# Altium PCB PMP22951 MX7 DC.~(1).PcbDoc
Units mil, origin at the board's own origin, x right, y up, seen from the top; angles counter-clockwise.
Board outline 4950 x 3450 mil, 2 copper layers (Top Layer, Bottom Layer), stack 62 mil thick; 24 components, 0 nets, 16 pads, 0 vias.
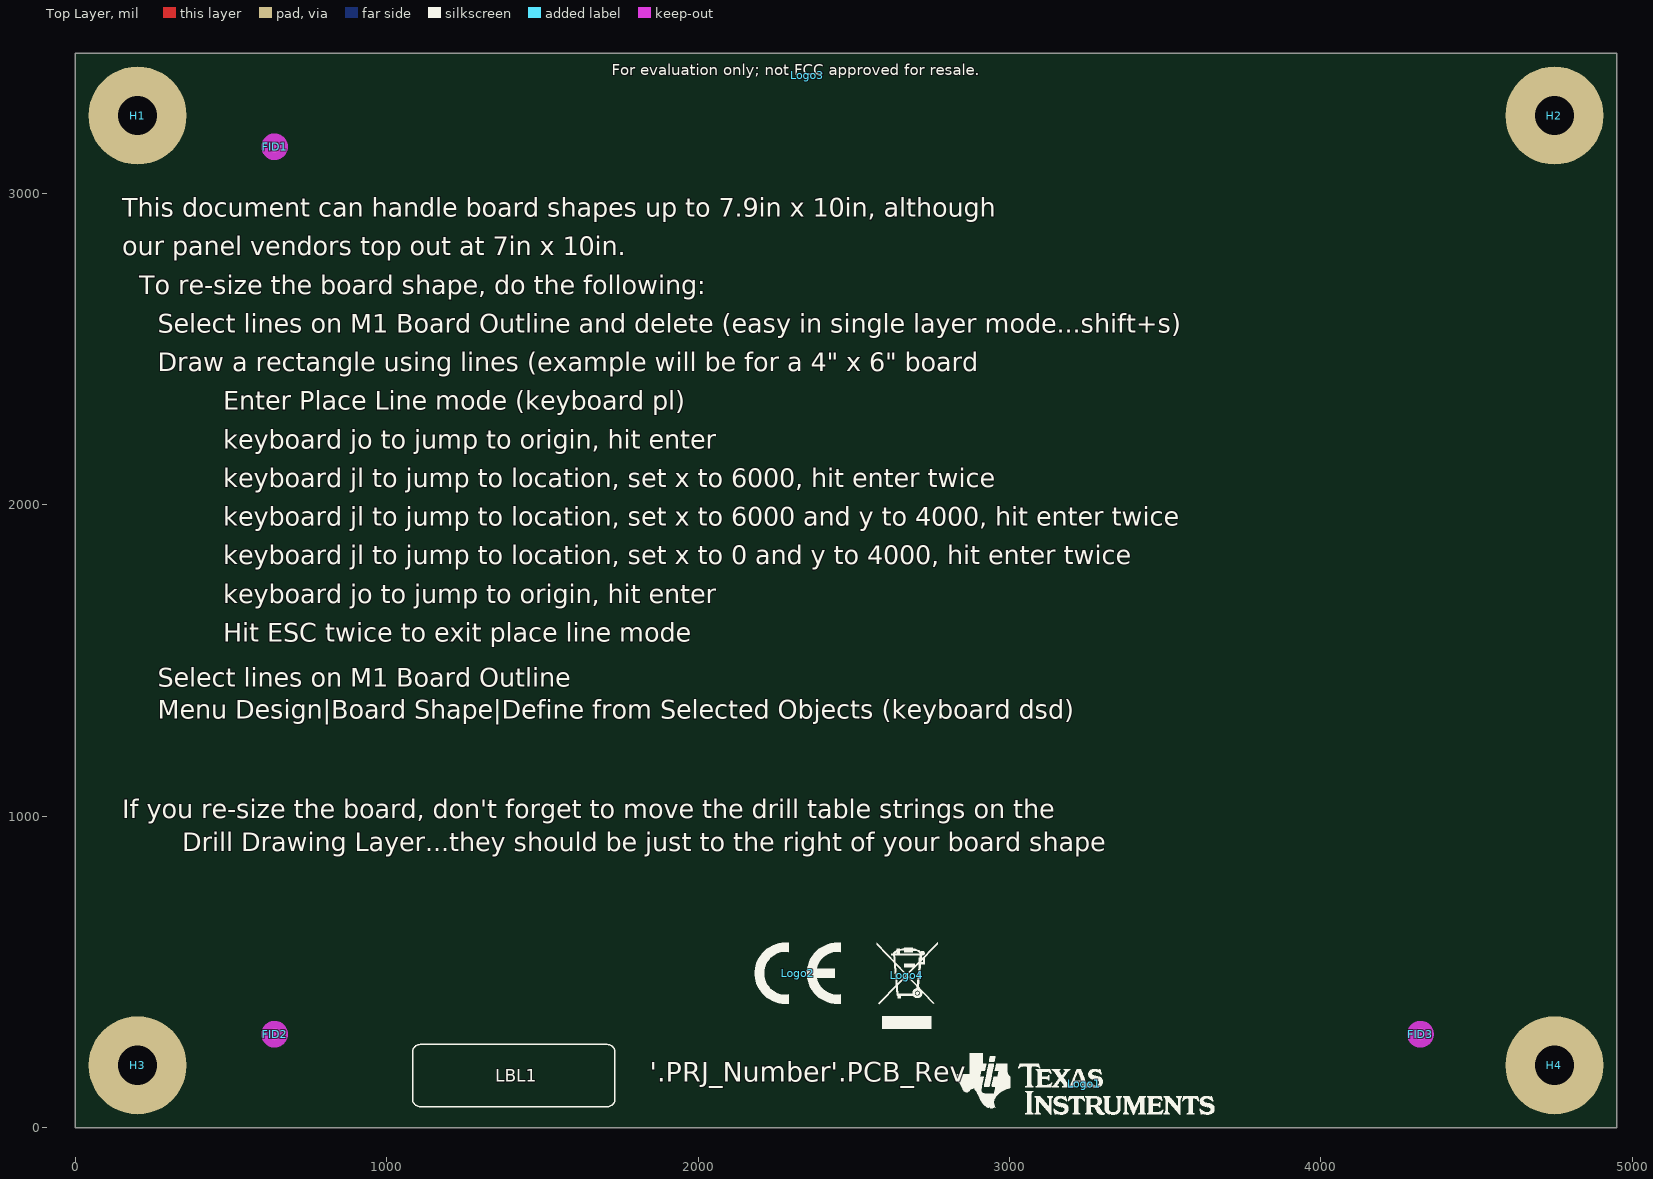
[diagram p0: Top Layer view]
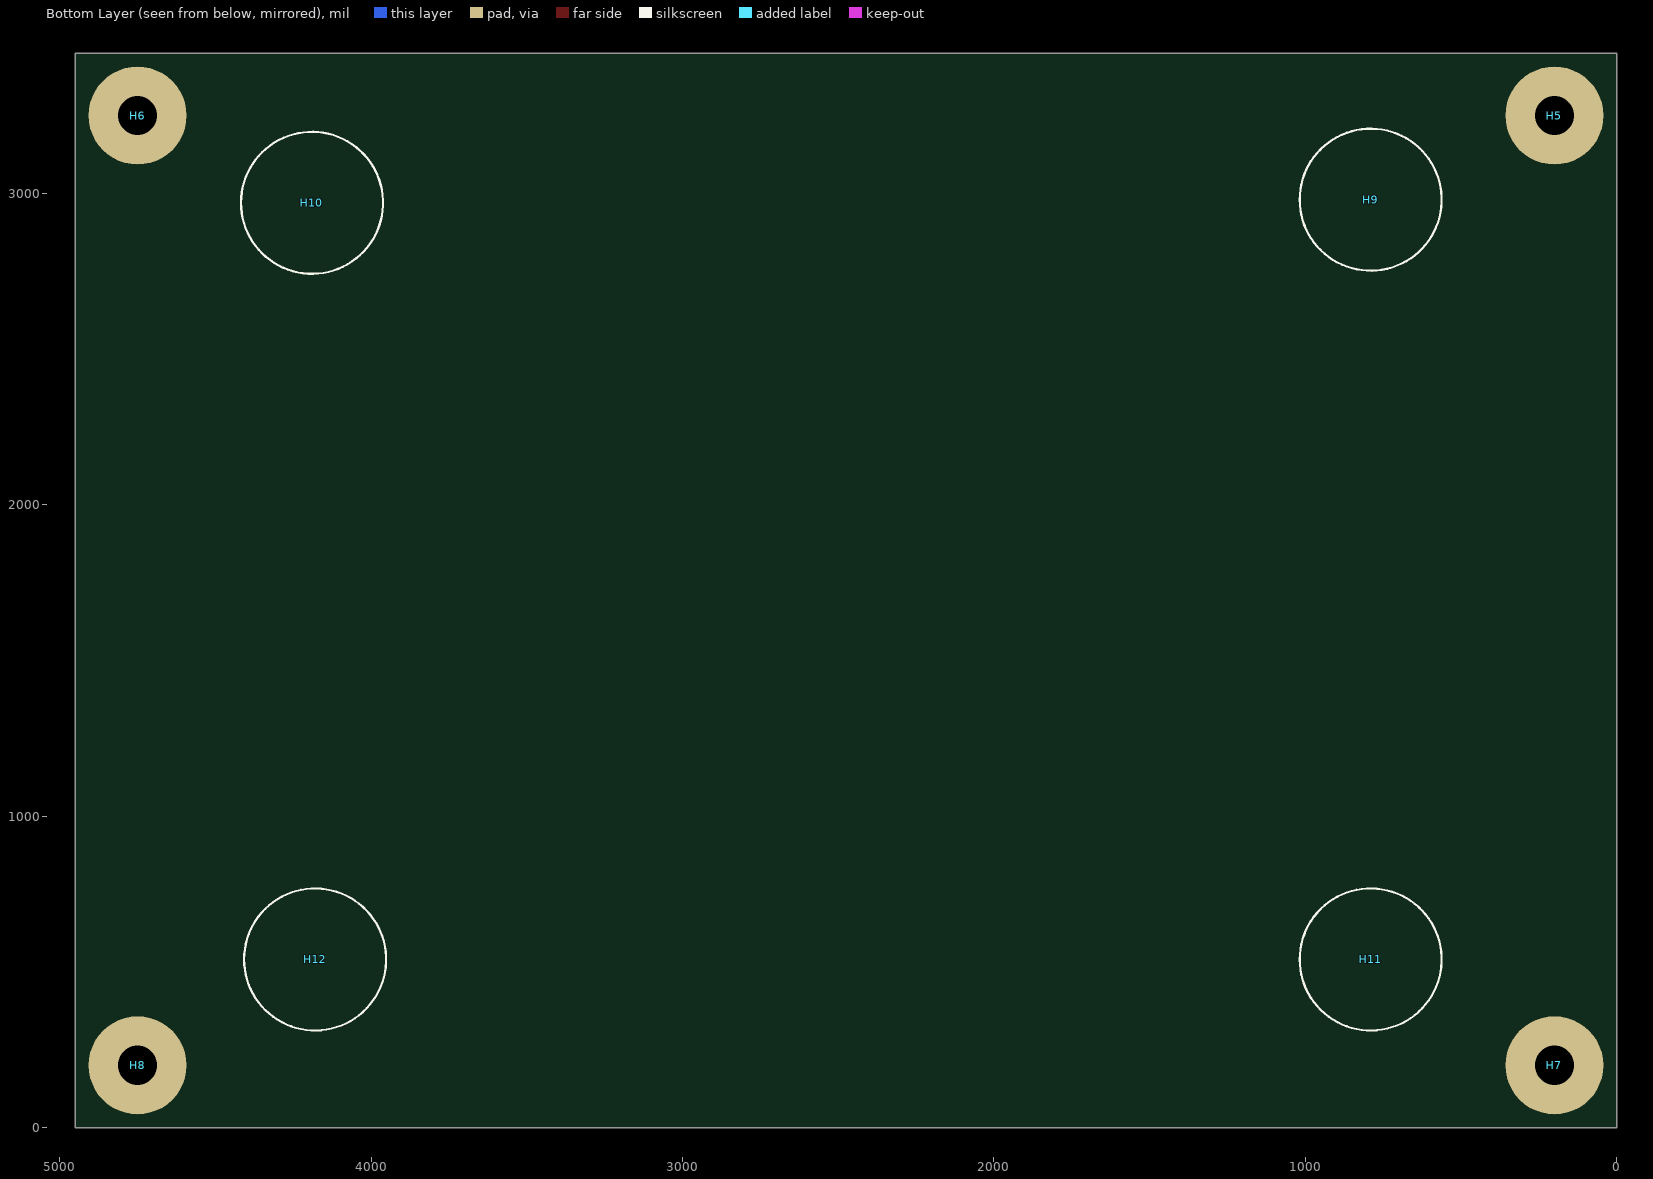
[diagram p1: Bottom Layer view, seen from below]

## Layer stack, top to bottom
Top Solder: solder mask 0.4, Solder Resist, Dk 3.5
Top Layer: signal copper 1.4
Dielectric1: core 59.2, FR-4 High Tg, Dk 4.8
Bottom Layer: signal copper 1.4
Bottom Solder: solder mask 0.4, Solder Resist, Dk 3.5

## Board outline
0,0 4950,0 4950,3450 0,3450

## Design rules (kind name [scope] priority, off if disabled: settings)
AcuteAngle [All] p1: minimum=4.50000000000000E+0001 checktracksonly=FALSE
AssemblyTestPointUsage [All] p1: valid=2
BoardOutlineClearance BoardOutlineClearance_MountingHoles [OnCopper and InComponentClass('Mounting Holes')] p1: gap=39.37 ignorepadtopadclearanceinfootprint=FALSE
BoardOutlineClearance BoardOutlineClearance_Poly [OnCopper and IsPoly] p2: gap=25 ignorepadtopadclearanceinfootprint=FALSE
BoardOutlineClearance [OnCopper and Not InComponentClass('Logo') and not InComponentClass('FiducialMark') and not InRegion(1000,500,4000,800) and not InPoly] p3: gap=40 ignorepadtopadclearanceinfootprint=FALSE
Clearance Clearance_Keepouts [((IsTrack Or IsArc) And Not InPoly) And IsFree and IsKeepOut vs ((IsTrack Or IsArc) And Not InPoly) And IsFree and IsKeepOut] p1: gap=0 ignorepadtopadclearanceinfootprint=FALSE
Clearance Clearance_Poly [InPolygon] p2: gap=10 ignorepadtopadclearanceinfootprint=TRUE
Clearance Clearance_FiducialMark [IsKeepOut and InComponentClass('FiducialMark') vs IsPad and InComponentClass('FiducialMark')] p3: gap=0 ignorepadtopadclearanceinfootprint=FALSE
Clearance [All] p4: gap=7.87 ignorepadtopadclearanceinfootprint=TRUE
ComponentClearance ComponentClearance_MountingHoles_FiducialMarks [InComponentClass('Mounting Holes') vs InComponentClass('FiducialMark')] p1: gap=50 collisioncheckmode=3 verticalgap=10 showdistances=FALSE
ComponentClearance ComponentClearance_Shunt [InComponentClass('Header') vs InComponentClass('Shunt')] p2: gap=0 collisioncheckmode=3 verticalgap=0 showdistances=FALSE
ComponentClearance ComponentClearance_Logo [InComponentClass('Logo')] p3: gap=30 collisioncheckmode=3 verticalgap=10 showdistances=FALSE
ComponentClearance ComponentClearance_ScrewToNut [(HasFootprint('NY PMS 440 0025 PH')) vs (HasFootprint('Keystone_1902C'))] p4: gap=5 collisioncheckmode=3 verticalgap=10 showdistances=FALSE
ComponentClearance ComponentClearance_MountingHoles [InComponentClass('Mounting Holes')] p5: gap=100 collisioncheckmode=3 verticalgap=100000 showdistances=FALSE
ComponentClearance ComponentClearance_SmallPassives [HasFootprint('0201*') or HasFootprint('0402*') or HasFootprint('0508') or HasFootprint('0603*') or HasFootprint('0612') or HasFootprint('0805*') or HasFootprint('0815*') or HasFootprint('0830*') or HasFootprint('1206*') or HasFootprint('1210*') or HasFootprint('1808*') or HasFootprint('1812*') or HasFootprint('1825*') or HasFootprint('2010*') or HasFootprint('2220*') or HasFootprint('2225*') or HasFootprint('2512*') or HasFootprint('2728*') or HasFootprint('3518*') vs HasFootprint('0201*') or HasFootprint('0402*') or HasFootprint('0508') or HasFootprint('0603*') or HasFootprint('0612') or HasFootprint('0805*') or HasFootprint('0815*') or HasFootprint('0830*') or HasFootprint('1206*') or HasFootprint('1210*') or HasFootprint('1808*') or HasFootprint('1812*') or HasFootprint('1825*') or HasFootprint('2010*') or HasFootprint('2220*') or HasFootprint('2225*') or HasFootprint('2512*') or HasFootprint('2728*') or HasFootprint('3518*')] p6: gap=14.96 collisioncheckmode=3 verticalgap=10 showdistances=FALSE
ComponentClearance ComponentClearance_THtoSMT [IsThruComponent vs IsSMTComponent] p7: gap=30 collisioncheckmode=3 verticalgap=30 showdistances=FALSE
ComponentClearance ComponentClearance_THtoTH [IsThruComponent vs IsThruComponent] p8: gap=20 collisioncheckmode=3 verticalgap=30 showdistances=FALSE
ComponentClearance [All] p9: gap=20 collisioncheckmode=3 verticalgap=10 showdistances=FALSE
DiffPairsRouting [All] p1: maxlimit=100 minlimit=10 mostfreqgap=10 toplayer_minwidth=15 toplayer_maxwidth=15 toplayer_prefwidth=15 bottomlayer_minwidth=15 bottomlayer_maxwidth=15 bottomlayer_prefwidth=15 maxuncoupledlength=1000
FabricationTestPointUsage TestPointUsage [All] p1: valid=2 allowmultiple=FALSE
FabricationTestpoint Testpoint [All] p1: side=3 testpointundercomponent=TRUE minsize=40 maxsize=100 preferedsize=60 minholesize=0 maxholesize=40 preferedholesize=32 testpointgrid=1 allowsidetop=TRUE allowsidebottom=TRUE usegrid=TRUE gridtolerance=0.01
FanoutControl Fanout_LCC [IsLCC] p1: bgadir=Out bgaviamode=Centered fanoutstyle=Auto fanoutdirection=Alternating viagrid=1 // Fanout_LCC (Default Rule)
FanoutControl Fanout_BGA [IsBGA] p2: bgadir=Out bgaviamode=Centered fanoutstyle=Auto fanoutdirection=Alternating viagrid=1 // Fanout_BGA (Default Rule)
FanoutControl Fanout_Default [All] p4: bgadir=Out bgaviamode=Centered fanoutstyle=Auto fanoutdirection=Alternating viagrid=1 // Fanout_Default (Default Rule)
FanoutControl Fanout_Small [(CompPinCount < 5)] p5: bgadir=Out bgaviamode=Centered fanoutstyle=Auto fanoutdirection=OutThenIn viagrid=1 // Fanout_Small (Default Rule)
HoleSize [All] p1: absolutevalues=TRUE maxlimit=251 minlimit=7.87 maxpercent=80.000 minpercent=20.000
MinimumAnnularRing MinimumAnnularRing_ThermalPadVias [IsVia and InAnyComponent] p1: minimumring=5.91
MinimumAnnularRing [All] p2: minimumring=7.87
MinimumSolderMaskSliver MinimumSolderMaskSliver_Logo [InComponentClass('Logo') vs InComponentClass('Logo')] p1: minsoldermaskwidth=0.7
MinimumSolderMaskSliver [All] p2: minsoldermaskwidth=3.94
PlaneConnect [All] p1: planeconnectstyle=Relief reliefexpansion=10 reliefentries=4 reliefconductorwidth=10 reliefairgap=10
PolygonConnect [All] p1: connectstyle=Relief reliefconductorwidth=10 reliefentries=4 polygonreliefangle="90 Angle" airgapwidth=10
RoutingVias ThermalPadVias [IsVia and InAnyComponent] p1: holewidth=7.87 width=19.68 viastyle="Through Hole" minholewidth=7.87 minwidth=19.68 maxholewidth=12.99 maxwidth=23.62
RoutingVias [All] p2: holewidth=16 width=34 viastyle="Through Hole" minholewidth=7.87 minwidth=24 maxholewidth=40 maxwidth=65
SilkToBoardRegionClearance [Not ((IsComment or IsDesignator) And (Hide <> 'False')) and not InRegion(1000,500,4000,800)] p1:
SilkToSilkClearance SilkToSilkClearance_Pb-FreeLogo [(HasFootprint('Pb-Free_Overlay_Medium') OR HasFootprint('Pb-Free_Overlay_Small')) vs (HasFootprint('Pb-Free_Overlay_Medium') OR HasFootprint('Pb-Free_Overlay_Small'))] p1: silktosilkclearance=0
SilkToSilkClearance [All] p2: silktosilkclearance=3.94
SilkToSolderMaskClearance SilkToComponentPadClearance [(IsPad or IsFill or IsRegion) and InAnycomponent] p1: minsilkscreentomaskgap=5 clearancetoexposedcopper=TRUE
SilkToSolderMaskClearance "Silk to Solder Mask Opening" [All] p2: minsilkscreentomaskgap=3.94 clearancetoexposedcopper=FALSE
SolderMaskExpansion [All] p1: expansion=1.97 istentingtop=FALSE
UnRoutedNet [All] p1: checkbadconnections=TRUE
Width [All] p1: maxlimit=100 minlimit=6 preferedwidth=10 checkconnectedcopper=TRUE
14 further rules are at their usual default settings.

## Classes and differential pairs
component class "Mounting Holes": H1 H2 H3 H4
component class Logo: Logo1
component class FiducialMark: FID1 FID2 FID3
component class AssemblyNote: ZZ1 ZZ2 ZZ3 ZZ4
component class Label: LBL1

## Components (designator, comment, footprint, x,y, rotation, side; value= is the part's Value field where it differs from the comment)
FID1 "Fiducial" Fiducial10-20 640,3150 r0 top
FID2 "Fiducial" Fiducial10-20 640,300 r0 top
FID3 "Fiducial" Fiducial10-20 4320,300 r0 top
H1 "NY PMS 440 0025 PH" "NY PMS 440 0025 PH" 200,3250 r0 top locked
H2 "NY PMS 440 0025 PH" "NY PMS 440 0025 PH" 4750,3250 r0 top locked
H3 "NY PMS 440 0025 PH" "NY PMS 440 0025 PH" 200,200 r0 top locked
H4 "NY PMS 440 0025 PH" "NY PMS 440 0025 PH" 4750,200 r0 top locked
H5 "1902C" Keystone_1902C 200,3250 r180 bottom locked
H6 "1902C" Keystone_1902C 4750,3250 r180 bottom locked
H7 "1902C" Keystone_1902C 200,200 r180 bottom locked
H8 "1902C" Keystone_1902C 4750,200 r180 bottom locked
H9 "SJ-5303 (CLEAR)" Bumpon_SJ5003Transparent 790,2980 r180 bottom
H10 "SJ-5303 (CLEAR)" Bumpon_SJ5003Transparent 4190,2970 r180 bottom
H11 "SJ-5303 (CLEAR)" Bumpon_SJ5003Transparent 790,540 r180 bottom
H12 "SJ-5303 (CLEAR)" Bumpon_SJ5003Transparent 4180,540 r180 bottom
LBL1 "THT-14-423-10" Label_650x200 1408,167 r0 top
Logo1 "Texas Instruments" TI_Stacked_Overlay_Small 3240,140 r0 top
Logo2 "CE Mark" CE_Mark_5mm 2320,495.68 r0 top
Logo3 "FCC disclaimer" FCC_disclaimer 2350,3380 r0 top
Logo4 "WEEE logo" WEEE_Minimum 2670,490 r0 top
ZZ1 "This Assembly Note is for PCB labels only" AssemblyNoteLabel 185,3938 r0 top
ZZ2 "These assemblies are ESD sensitive, ESD precautions shall be observed." AssemblyNote 185,3829.11 r0 top
ZZ3 "These assemblies must be clean and free from flux and all contaminants. Use of no clean flux is not acceptable." AssemblyNote 185,3740.56 r0 top
ZZ4 "These assemblies must comply with workmanship standards IPC-A-610 Class 2, unless otherwise specified." AssemblyNote 185,3652 r0 top

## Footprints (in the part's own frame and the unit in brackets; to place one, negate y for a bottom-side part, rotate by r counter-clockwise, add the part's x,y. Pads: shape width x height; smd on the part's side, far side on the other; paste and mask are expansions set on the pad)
AssemblyNote [mil] "Assembly Note"
AssemblyNoteLabel [mil] "Assembly Note for PCB Labels"
Bumpon_SJ5003Transparent [mil] "3M Hemispherical Bumpon transparent"
  round 1 on Mech4: 0(0,0)
  silkscreen extent -228,-228 228,228, body extent -219,-219 219,219, height 197
CE_Mark_5mm [mil] "Minimum text height for CE Mark"
  silkscreen extent -138,-98 138,98
FCC_disclaimer [mil]
Fiducial10-20 [mm]
  round 1 smd mask+0.5: 1(0,0)
  Top Layer keep-out circle w1.178: c0,0 r0.5
Keystone_1902C [mil] "Hex Standoff, 4-40 threaded, nylon"
  round 1 on Mech4: 0(0,0)
  body extent -145,-126 146,126, height 501
Label_650x200 [mil] "Thermal Transfer Label"
  round 1 on Mech13: 0(0,0)
  silkscreen extent -325,-100 325,100, body extent -325,-100 325,100, height 1
"NY PMS 440 0025 PH" [mm] "4-40 nylon screw and mounting hole"
  round 8 hole 3.2: 1(0,0)
  body extent -3.3,-3.3 3.3,3.3, height 2.69
TI_Stacked_Overlay_Small [mil]
  silkscreen extent -418,-98 418,98
WEEE_Minimum [mil] "WEEElie bin"
  silkscreen extent -95,-172 99,104

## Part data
FID1 FID2 FID3: library part CMP-0077181-1, "Fiducial mark.  There is nothing to buy or mount.", Manufacturer=N/A
H1 H2 H3 H4: library part CMP-0003617-1, "Machine Screw, Round, #4-40 x 1/4, Nylon, Philips panhead", Manufacturer="B&F Fastener Supply", Supplier Part Number 1=H542-ND
H5 H6 H7 H8: library part CMP-0003610-1, "Standoff, Hex, 0.5\"L #4-40 Nylon", Manufacturer=Keystone, Supplier Part Number 1=36-1902C-ND
H9 H10 H11 H12: library part CMP-0003620-1, "Bumpon, Hemisphere, 0.44 X 0.20, Clear", Manufacturer=3M, Supplier Part Number 1=SJ5303-7-ND
LBL1: library part CMP-0003625-1, "Thermal Transfer Printable Labels, 0.650\" W x 0.200\" H - 10,000 per roll", Manufacturer=Brady, Supplier Part Number 1=97C5133
Logo1: library part CMP-0074838-1, "Texas Instrument Corporate Signature"
Logo2: library part CMP-0074844-1
Logo3: library part CMP-0074847-1, "FCC_disclaimer"
Logo4: library part CMP-0074769-1
ZZ1: library part CMP-0003616-3
ZZ2: library part CMP-0077236-1
ZZ3: library part CMP-0077237-1
ZZ4: library part CMP-0077238-1

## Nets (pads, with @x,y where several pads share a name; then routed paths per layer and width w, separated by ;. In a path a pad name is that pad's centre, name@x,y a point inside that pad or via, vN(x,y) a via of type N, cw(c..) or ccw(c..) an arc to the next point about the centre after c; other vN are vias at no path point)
pads on no net: FID1.1 FID2.1 FID3.1 H1.1 H2.1 H3.1 H4.1 H5.0 H6.0 H7.0 H8.0 H9.0 H10.0 H11.0 H12.0 LBL1.0

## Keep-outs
Keep-Out Layer:
  text ".Layer_Name" at 577,-858.49 h60

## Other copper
Top Layer:
  text ".Layer_Name" at 577,-858.49 h60
Bottom Layer:
  text ".Layer_Name" at 577,-858.49 h60

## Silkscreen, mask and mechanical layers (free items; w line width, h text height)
Top Overlay:
  text "This document can handle board shapes up to 7.9in x 10in, although" at 150,2925 h60
  text "our panel vendors top out at 7in x 10in." at 150,2800.94 h60
  text "To re-size the board shape, do the following:" at 205,2676.88 h60
  text "Select lines on M1 Board Outline and delete (easy in single layer mode...shift+s)" at 265,2552.82 h60
  text "Draw a rectangle using lines (example will be for a 4\" x 6\" board" at 265,2428.76 h60
  text "Enter Place Line mode (keyboard pl)" at 475,2304.71 h60
  text "keyboard jo to jump to origin, hit enter" at 475,2180.65 h60
  text "keyboard jl to jump to location, set x to 6000, hit enter twice" at 475,2056.59 h60
  text "keyboard jl to jump to location, set x to 6000 and y to 4000, hit enter twice" at 475,1932.53 h60
  text "keyboard jl to jump to location, set x to 0 and y to 4000, hit enter twice" at 475,1808.47 h60
  text "keyboard jo to jump to origin, hit enter" at 475,1684.41 h60
  text "Hit ESC twice to exit place line mode" at 475,1560.35 h60
  text "Select lines on M1 Board Outline" at 265,1416.3 h60
  text "Menu Design|Board Shape|Define from Selected Objects (keyboard dsd)" at 265,1312.24 h60
  text "If you re-size the board, don't forget to move the drill table strings on the" at 150,993 h60
  text "Drill Drawing Layer...they should be just to the right of your board shape" at 343,887 h60
  text "'.PRJ_Number'.PCB_Rev" at 1845,125.77 h108.27
  text ".Layer_Name" at 577,-858.49 h60
Bottom Overlay:
  text ".Layer_Name" at 577,-858.49 h60
Top Paste:
  text ".Layer_Name" at 577,-858.49 h60
Bottom Paste:
  text ".Layer_Name" at 577,-858.49 h60
Top Solder:
  text ".Layer_Name" at 577,-858.49 h60
  text ".Layer_Name" at 577,-858.49 h60
Bottom Solder:
  text ".Layer_Name" at 577,-858.49 h60
Drill Guide:
  text ".Layer_Name" at 577,-858.49 h60
M1 Board Outline:
  the board outline again, w10
  text ".Layer_Name" at 577,-858.49 h60
M2 Board Dimensions:
  rectangle: 0,-275 125,-150
  rectangle: 125,-400 500,-275
  lines w7: 0,-275 1000,-275 ; 125,-400 125,-150 ; 250,-400 250,-150 ; 500,-400 500,-150 ; 750,-400 750,-150 ; 0,-400 1000,-400 1000,-150 0,-150 0,-400
  text ".Layer_Name" at 577,-858.49 h60
M3 3D STEP Top:
  text ".Layer_Name" at 577,-858.49 h60
M4 3D STEP Bottom:
  text ".Layer_Name" at 577,-858.49 h60
M5 Assembly Top:
  lines w10: -292,-930.17 6308,-930.17 ; -292,-726.83 6310,-726.83 ; -292,-523.5 -292,-1133.5 3713,-1133.5 6310,-1133.5 6310,-523.5 -291.5,-523.5 -291.5,-1133.5 1284,-1133.5 ; 2173,-1133.5 2173,-523.5 ; 3440,-726.83 3440,-523.5 ; 4280,-726.83 4280,-523.5 ; 4902,-1140 4902,-937.17
  text "COMPONENTS MARKED 'DNP' SHOULD NOT BE POPULATED." at 1153.5,-318.5 h60
  text "ASSEMBLY VARIANT:" at 1153,-434 h60
  text ".VariantName" at 2189,-434 h60
  text "PCB VIEWED FROM TOP SIDE" at -228.5,-655.67 h60
  text "BOARD #:" at 2248,-655.67 h60
  text ".PRJ_Number" at 2793.5,-655.67 h60
  text "REV:" at 3638,-655.67 h60
  text ".PCB_Rev" at 3929.5,-655.67 h60
  text "SVN REV:" at 4476,-655.67 h60
  text ".VersionControl_RevNumber" at 4982,-655.67 h60
  text "TID #:" at 2248,-859 h60
  text ".TID" at 2793.5,-859 h60
  text "PLOT NAME =" at -228.5,-1064.34 h60
  text ".plot_File_Name" at 577,-1064.34 h60
  text "GENERATED    :" at 2250,-1064.34 h60
  text ".Print_Date" at 3119.5,-1064.34 h60
  text ".Print_Time" at 3848.5,-1064.34 h60
  text "TEXAS INSTRUMENTS" at 5113,-1064.34 h60
M6 Assembly Bottom:
  lines w10: -292.5,-727.33 6309.5,-727.33 ; -290.5,-930.67 6309.5,-930.67 ; 1115.5,-1140.5 1115.5,-937.67 ; 1737.5,-727.33 1737.5,-524 ; 2577.5,-727.33 2577.5,-524 ; 3844.5,-1134 3844.5,-524 ; 4733.5,-1134 6309,-1134 6309,-524 -292.5,-524 -292.5,-1134 2304.5,-1134 6309.5,-1134 6309.5,-524
  text "COMPONENTS MARKED 'DNP' SHOULD NOT BE POPULATED." at 6102,-318 h60
  text ".VariantName" at 5058,-434 h60
  text "ASSEMBLY VARIANT:" at 6097,-434 h60
  text ".VersionControl_RevNumber" at 1035.5,-656.17 h60
  text "SVN REV:" at 1541.5,-656.17 h60
  text ".PCB_Rev" at 2088,-656.17 h60
  text "REV:" at 2379.5,-656.17 h60
  text ".PRJ_Number" at 3224,-656.17 h60
  text "BOARD #:" at 3769.5,-656.17 h60
  text "PCB VIEWED FROM BOTTOM SIDE" at 6246,-656.17 h60
  text ".TID" at 3224,-859.5 h60
  text "TID #:" at 3769.5,-859.5 h60
  text "TEXAS INSTRUMENTS" at 904.5,-1064.84 h60
  text ".Print_Time" at 2169,-1064.84 h60
  text ".Print_Date" at 2898,-1064.84 h60
  text "GENERATED    :" at 3767.5,-1064.84 h60
  text ".plot_File_Name" at 5440.5,-1064.84 h60
  text "PLOT NAME =" at 6246,-1064.84 h60
M9 Title Sheet:
  drawing of 57 lines, arcs and shapes, not listed
  text "1" at 739.84,8036.5 h70
  text "2" at 3235.5,8036.5 h70
  text "3" at 5724.84,8036.5 h70
  text "4" at 8231.51,8036.5 h70
  text "5" at 10730.5,8036.5 h70
  text "6" at 13235.5,8036.5 h70
  text "A" at -416.5,6893.5 h70
  text "A" at 14383.5,6893.5 h70
  text "B" at -416.5,4513.5 h70
  text "B" at 14383.5,4513.5 h70
  text "C" at -416.5,2138.5 h70
  text "C" at 14383.5,2138.5 h70
  text "PROJECT TITLE:" at 11343.5,277.5 h45
  text ".PRJ_Title" at 11393.5,144.17 h70
  text "DESIGNED FOR:" at 11343.5,-23.5 h45
  text ".PRJ_Customer" at 11393.5,-163.5 h70
  text "D" at -416.5,-231.5 h70
  text "D" at 14383.5,-231.5 h70
  text "FILE NAME:" at 11343.5,-323.5 h45
  text ".PCB_File_Name_No_Path" at 11393.5,-443.5 h70
  text "Texas Instruments (TI) and/or its licensors do not warrant the accuracy or completeness of this specification" at 6374,-605.34 h45
  text "ENGINEER:" at 11343.5,-613.5 h45
  text "LAYOUT BY:" at 12848.5,-613.5 h45
  text "or any information contained therein. TI and/or its licensors do not warrant that this design will meet" at 6329.01,-718 h45
  text ".PRJ_Engineer" at 11393.5,-768.49 h70
  text ".PCB_Layout" at 12899,-768.49 h70
  text "the specifications, will be suitable for your application or fit for any particular purpose, or will operate in" at 6329.01,-830.67 h45
  text ".Layer_Name" at 577,-858.49 h60
  text "ALTIUM DESIGNER VERSION:" at 12848.5,-923.5 h45
  text "an implementation. TI and/or its licensors do not warrant that the design is production worthy. You should" at 6329.01,-943.33 h45
  text "completely validate and test your design implementation to confirm the system functionality for your application." at 6374,-1056 h45
  text ".print_Scale" at 11393.5,-1056.83 h70
  text ".Application_BuildNumber" at 12899,-1056.83 h70
  text "1" at 739.84,-1263.5 h70
  text "2" at 3235.5,-1263.5 h70
  text "3" at 5724.84,-1263.5 h70
  text "4" at 8231.51,-1263.5 h70
  text "5" at 10730.5,-1263.5 h70
  text "6" at 13235.5,-1263.5 h70
M10 Fab Notes:
  drawing of 189 lines, arcs and shapes, not listed
  text "DESIGN INFORMATION" at 12382.02,6356.17 h60
  text "MIN. TRACK WIDTH:" at 11737.46,6224.05 h60
  text "8" at 12833.7,6224.05 h60
  text "MIL" at 12988.46,6224.05 h60
  text "7.874" at 12667.32,6102.36 h60
  text "MIN. CLEARANCE:" at 11737.46,6099.92 h60
  text "MIL" at 12988.46,6099.92 h60
  text "MIN. VIA PAD SIZE:" at 11737.46,5975.8 h60
  text "24" at 12803.71,5975.8 h60
  text "MIL" at 12988.46,5975.8 h60
  text "0.05mm (2MIL)" at 12432.46,5845.9 h60
  text "MINIMUM ANNULAR RING" at 11408.23,5837.67 h60
  text "EXTERNAL" at 13140.46,5837.67 h60
  text "PER" at 11608.23,5727.55 h60
  text "IPC-D-275 CLASS 2 LEVEL C" at 11828.23,5727.54 h60
  text "MIL, HOLES" at 13316.46,5627.07 h60
  text "+/-" at 12924,5618.48 h60
  text "+/-" at 13778,5618.48 h60
  text "REGISTRATION TOLERANCES:" at 11408.23,5617.42 h60
  text "METAL" at 12608,5617.42 h60
  text "5" at 13184.2,5617.42 h60
  text "3" at 14017.2,5617.42 h60
  text "MIL" at 14133.46,5617.42 h60
  text "HOLE SIZE TOLERANCE (UNLESS OTHERWISE SPECIFIED):" at 11408.23,5519.1 h60
  text "+/-" at 13778,5516.23 h60
  text "3" at 14017.2,5515.17 h60
  text "MIL" at 14133.46,5515.17 h60
  text "MATERIAL:" at 11333.46,5377.52 h60
  text "FR-4 High Tg" at 12319.9,5249 h60
  text "X" at 12175.46,5241.01 h60
  text "FR-4" at 11754.46,5236.49 h60
  text "OTHER" at 13242.46,5236.49 h60
  text "62 MIL (1.6mm) +/-10%" at 12074.56,5093.46 h60
  text "X" at 11954.46,5091.01 h60
  text "THICKNESS:" at 11408.23,5085.24 h60
  text "OTHER" at 13359.46,5085.24 h60
  text "TOLERANCE:" at 11408.23,4946.92 h60
  text "X" at 12256.46,4946.92 h60
  text "ANSI IPC-6012 TYPE 3 CLASS 2" at 12434.48,4946.92 h60
  text "OTHER +/-" at 12434.46,4802.73 h60
  text "BOW & TWIST:" at 11408.23,4657.54 h60
  text "X" at 12256.46,4657.54 h60
  text "ANSI IPC-6012 TYPE 3 CLASS 2" at 12434.48,4657.54 h60
  text "OTHER +/-" at 12434.46,4510.85 h60
  text "DRILLING:" at 11333.46,4380.23 h60
  text "NC_DRILL FILES" at 13094.46,4275.04 h60
  text "REFERENCE:" at 11408.23,4271.1 h60
  text "X" at 12065.46,4271.01 h60
  text "AS SHOWN" at 12243.46,4271.1 h60
  text "X" at 12966.46,4271.1 h60
  text "OTHER" at 13392.46,4128.85 h60
  text "PTH COPPER THICKNESS:" at 11407.91,4125.32 h60
  text "X" at 12547.14,4125.32 h60
  text "20-30 um" at 12675.14,4125.32 h60
  text "BOARD FINISH:" at 11333.46,3977.73 h60
  text "SILKSCREEN:" at 11488.68,3867.6 h60
  text "X" at 12446.46,3867.6 h60
  text "TOP" at 12563.46,3867.6 h60
  text "X" at 12956.46,3867.6 h60
  text "BOTTOM" at 13074.46,3867.6 h60
  text "SILKSCREEN COLOR:" at 11488.68,3712.41 h60
  text "X" at 12445.46,3712.41 h60
  text "WHITE" at 12563.46,3712.41 h60
  text "OTHER" at 13074.46,3712.41 h60
  text "X" at 12576.46,3568.96 h60
  text "GREEN" at 12694.46,3568.96 h60
  text "OTHER" at 13312.46,3568.96 h60
  text "SOLDER RESIST COLOR:" at 11488.68,3562.1 h60
  text "X" at 12576.46,3414.71 h60
  text "MATTE" at 12694.46,3414.71 h60
  text "SEMI-GLOSS" at 13312,3414.07 h60
  text "IMMERSION GOLD (ENIG)" at 12394.46,3241.94 h60
  text "ENEPIG" at 13732,3234.72 h60
  text "SURFACE FINISH:" at 11333.46,3233.72 h60
  text "X" at 12216.46,3233.72 h60
  text "IMM. TIN/SILVER OR EQUIV" at 11663,3096.4 h60
  text "OTHER" at 13094.46,3092.47 h60
  text "ARRAY/PANEL:" at 11333.46,2937.09 h60
  text "CUT AND TRIM PER M1 BOARD OUTLINE" at 12394.46,2928.87 h60
  text "N.C. ROUTE" at 12394.46,2792.9 h60
  text "X" at 13082.46,2792.9 h60
  text "V. SCORE" at 13260.46,2792.9 h60
  text "CERTIFICATION:" at 11333.46,2663.77 h60
  text "MATERIALS AND WORKMANSHIP FOR ALL PCBS" at 12058.46,2663.77 h60
  text "TO MEET OR EXCEED THE REQUIREMENTS OF:" at 12058.46,2569.71 h60
  text "X" at 11695.97,2441.08 h60
  text "ANSI IPC-A-600F CLASS ->" at 11823.96,2441.08 h60
  text "X" at 13471.97,2441.08 h60
  text "2" at 13581.96,2441.08 h60
  text "1" at 13266.96,2439.58 h60
  text "3" at 13935.96,2439.58 h60
  text "X" at 12507.97,2293.39 h60
  text "RoHS" at 12635.96,2293.39 h60
  text "OTHER" at 13280.36,2293.39 h60
  text "PER ORDER" at 13677.42,2293.39 h60
  text "ALL BOARDS MUST MEET OR EXCEED UL94-V0 REQUIREMENTS." at 11361,2139.57 h60
  text "PCB MUST BEAR THE UL94V-0 UL REGISTERED MATERIAL ID NUMBER" at 11361,2023.5 h60
  text "ADDITIONAL REQUIREMENTS:" at 11333.46,1854.08 h60
  text "MICROSECTION:" at 11408.23,1746.95 h60
  text "YES" at 12313.96,1746.95 h60
  text "REQUIRED" at 13175.46,1602.62 h60
  text "BARE BOARD ELEC. TEST:" at 11408.23,1599.76 h60
  text "NONE" at 12713.96,1599.76 h60
  text "X" at 13057.46,1599.76 h60
  text "PER ORDER" at 13767.46,1599.76 h60
  text "XX MIL VIAS REQUIRE NON-CONDUCTIVE FILL AND PLANARIZE" at 11576.38,1394.82 h59
  text "XX MIL VIAS REQUIRE CONDUCTIVE FILL AND PLANARIZE" at 11584.38,1290.84 h60
  text "OUTER XX MIL TRACES REQUIRE 50 OHM SINGLE-ENDED IMPEDANCE" at 11583.39,1127.46 h58
  text "LAYER 2 & 3 (INNER LAYERS) XX MIL WIDE, XX MIL SPACE / TRACES REQUIRE 100 OHM DIFFERENTIAL IMPEDANCE" at 11575.39,891.74 h60
  text ".Layer_Name" at 577,-858.49 h60
M11 Gerber Information:
  lines w10: -292,-930.17 6308,-930.17 ; -292,-726.83 6310,-726.83 ; -292,-523.5 -292,-1133.5 3713,-1133.5 6310,-1133.5 6310,-523.5 -291.5,-523.5 -291.5,-1133.5 1284,-1133.5 ; 2173,-1133.5 2173,-523.5 ; 3440,-726.83 3440,-523.5 ; 4280,-726.83 4280,-523.5 ; 4902,-1140 4902,-937.17
  text "ALL ARTWORK VIEWED FROM TOP SIDE" at -228.5,-655.67 h60
  text "BOARD #:" at 2248,-655.67 h60
  text ".PRJ_Number" at 2793.5,-655.67 h60
  text "REV:" at 3638,-655.67 h60
  text ".PCB_Rev" at 3929.5,-655.67 h60
  text "SVN REV:" at 4476,-655.67 h60
  text ".VersionControl_RevNumber" at 4982,-655.67 h60
  text "LAYER NAME =" at -228.5,-858.49 h60
  text "TID #:" at 2248,-859 h60
  text ".TID" at 2793.5,-859 h60
  text "PLOT NAME =" at -228.5,-1064.34 h60
  text ".plot_File_Name" at 577,-1064.34 h60
  text "GENERATED    :" at 2250,-1064.34 h60
  text ".Print_Date" at 3119.5,-1064.34 h60
  text ".Print_Time" at 3848.5,-1064.34 h60
  text "TEXAS INSTRUMENTS" at 5113,-1064.34 h60
M12 Stackup:
  drawing of 191 lines, arcs and shapes, not listed
  text "Layer" at 9821.59,7874.94 h60
  text "Name" at 10231.51,7874.94 h60
  text "Material" at 11161.25,7874.94 h60
  text "Thickness" at 12021.02,7874.94 h60
  text "Constant" at 12670.85,7874.94 h60
  text "Board Layer Stack" at 13240.71,7874.94 h60
  text "Top Overlay" at 10231.51,7754.94 h60
  text "Top Solder" at 10231.51,7634.94 h60
  text "Solder Resist" at 11161.25,7634.94 h60
  text "0.40mil" at 12021.02,7634.94 h60
  text "3.5" at 12670.85,7634.94 h60
  text "1" at 9821.59,7514.94 h60
  text "Top Layer" at 10231.51,7514.94 h60
  text "1.40mil" at 12021.02,7514.94 h60
  text "Dielectric1" at 10231.51,7394.94 h60
  text "FR-4 High Tg" at 11161.25,7394.94 h60
  text "59.20mil" at 12021.02,7394.94 h60
  text "4.8" at 12670.85,7394.94 h60
  text "2" at 9821.59,7274.94 h60
  text "Bottom Layer" at 10231.51,7274.94 h60
  text "1.40mil" at 12021.02,7274.94 h60
  text "Bottom Solder" at 10231.51,7154.94 h60
  text "Solder Resist" at 11161.25,7154.94 h60
  text "0.40mil" at 12021.02,7154.94 h60
  text "3.5" at 12670.85,7154.94 h60
  text "Bottom Overlay" at 10231.51,7034.94 h60
  text ".Layer_Name" at 577,-858.49 h60
M13 Component Bodies Top:
  text ".Layer_Name" at 577,-858.49 h60
M14 Component Bodies Bottom:
  text ".Layer_Name" at 577,-858.49 h60
M15 Courtyards Top:
  text ".Layer_Name" at 577,-858.49 h60
M16 Courtyards Bottom:
  text ".Layer_Name" at 577,-858.49 h60
Drill Drawing:
  circle w10: c5363.63,3290.5 r27.59
  lines w12: 5286,3225.65 8516.52,3225.65 ; 5286,3349.82 8516.52,3349.82 ; 5623.86,3101.47 5623.86,3474 ; 5955.86,3101.47 5955.86,3474 ; 6592.42,3101.47 6592.42,3474 ; 6851.53,3101.47 6851.53,3474 ; 7226.68,3101.47 7226.68,3474 ; 7950.06,3101.47 7950.06,3474 ; 5286,3101.47 8516.52,3101.47 8516.52,3474 5286,3474 5286,3101.47
  text "Symbol" at 5360.51,3387.08 h72
  text "Quantity" at 5661.11,3387.08 h72
  text "Finished Hole Size" at 5993.12,3387.08 h72
  text "Plated" at 6629.67,3387.08 h72
  text "Hole Type" at 6888.78,3387.08 h72
  text "Drill Layer Pair" at 7263.93,3387.08 h72
  text "Hole Tolerance" at 7987.32,3387.08 h72
  text "4" at 5661.11,3262.9 h60
  text "125.98mil (3.200mm)" at 5993.12,3262.9 h60
  text "PTH" at 6629.67,3262.9 h60
  text "Round" at 6888.78,3262.9 h60
  text "Top Layer - Bottom Layer" at 7263.93,3262.9 h60
  text "4 Total" at 5661.11,3138.72 h60
  text ".Layer_Name" at 577,-858.49 h60
M17 Embedded Cavity:
  text ".Layer_Name" at 577,-858.49 h60
M18 Embedded Assembly:
  text ".Layer_Name" at 577,-858.49 h60
M19 Embedded Keepout:
  text ".Layer_Name" at 577,-858.49 h60

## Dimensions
0,-400 to 1000,-400 on M2 Board Dimensions
0,0 to 0,3450 on M2 Board Dimensions
0,0 to 4950,0 on M2 Board Dimensions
